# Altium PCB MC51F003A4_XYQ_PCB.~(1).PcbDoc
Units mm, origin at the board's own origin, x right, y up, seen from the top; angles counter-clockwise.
Board outline 55.25 x 35.69 mm, 2 copper layers (Top Layer, Bottom Layer); 32 components, 23 nets, 110 pads, 48 vias.
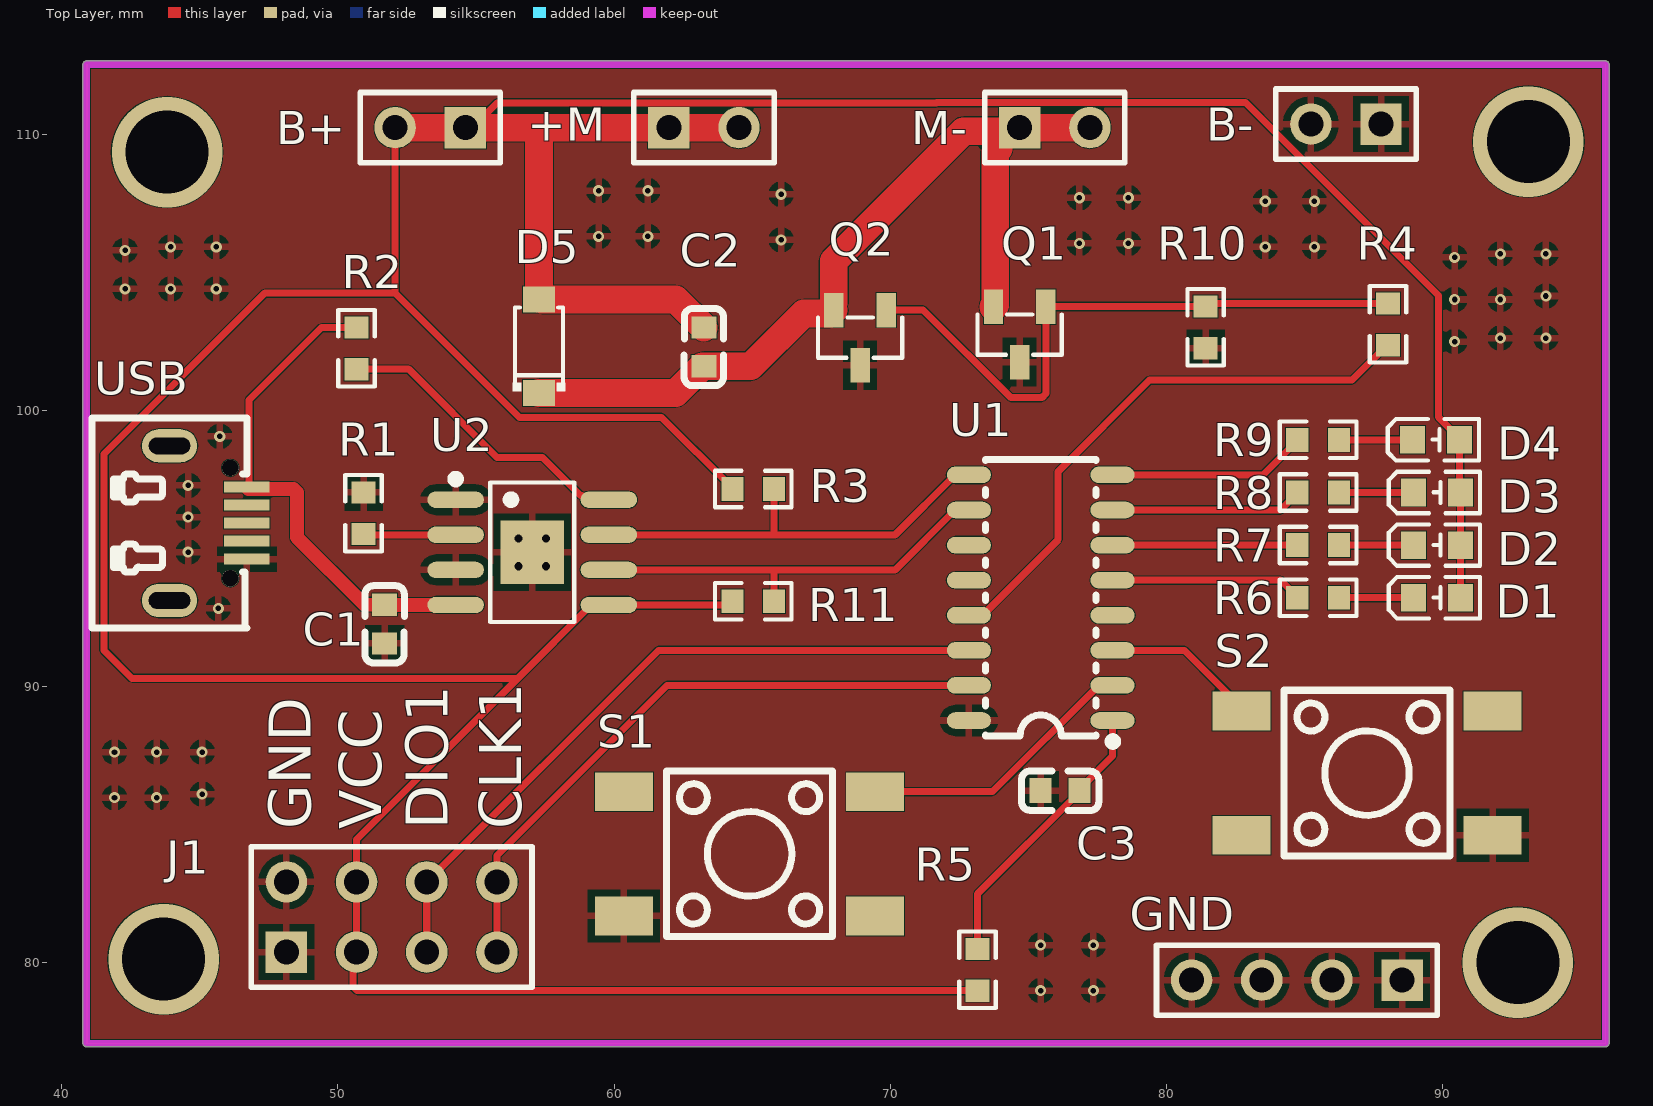
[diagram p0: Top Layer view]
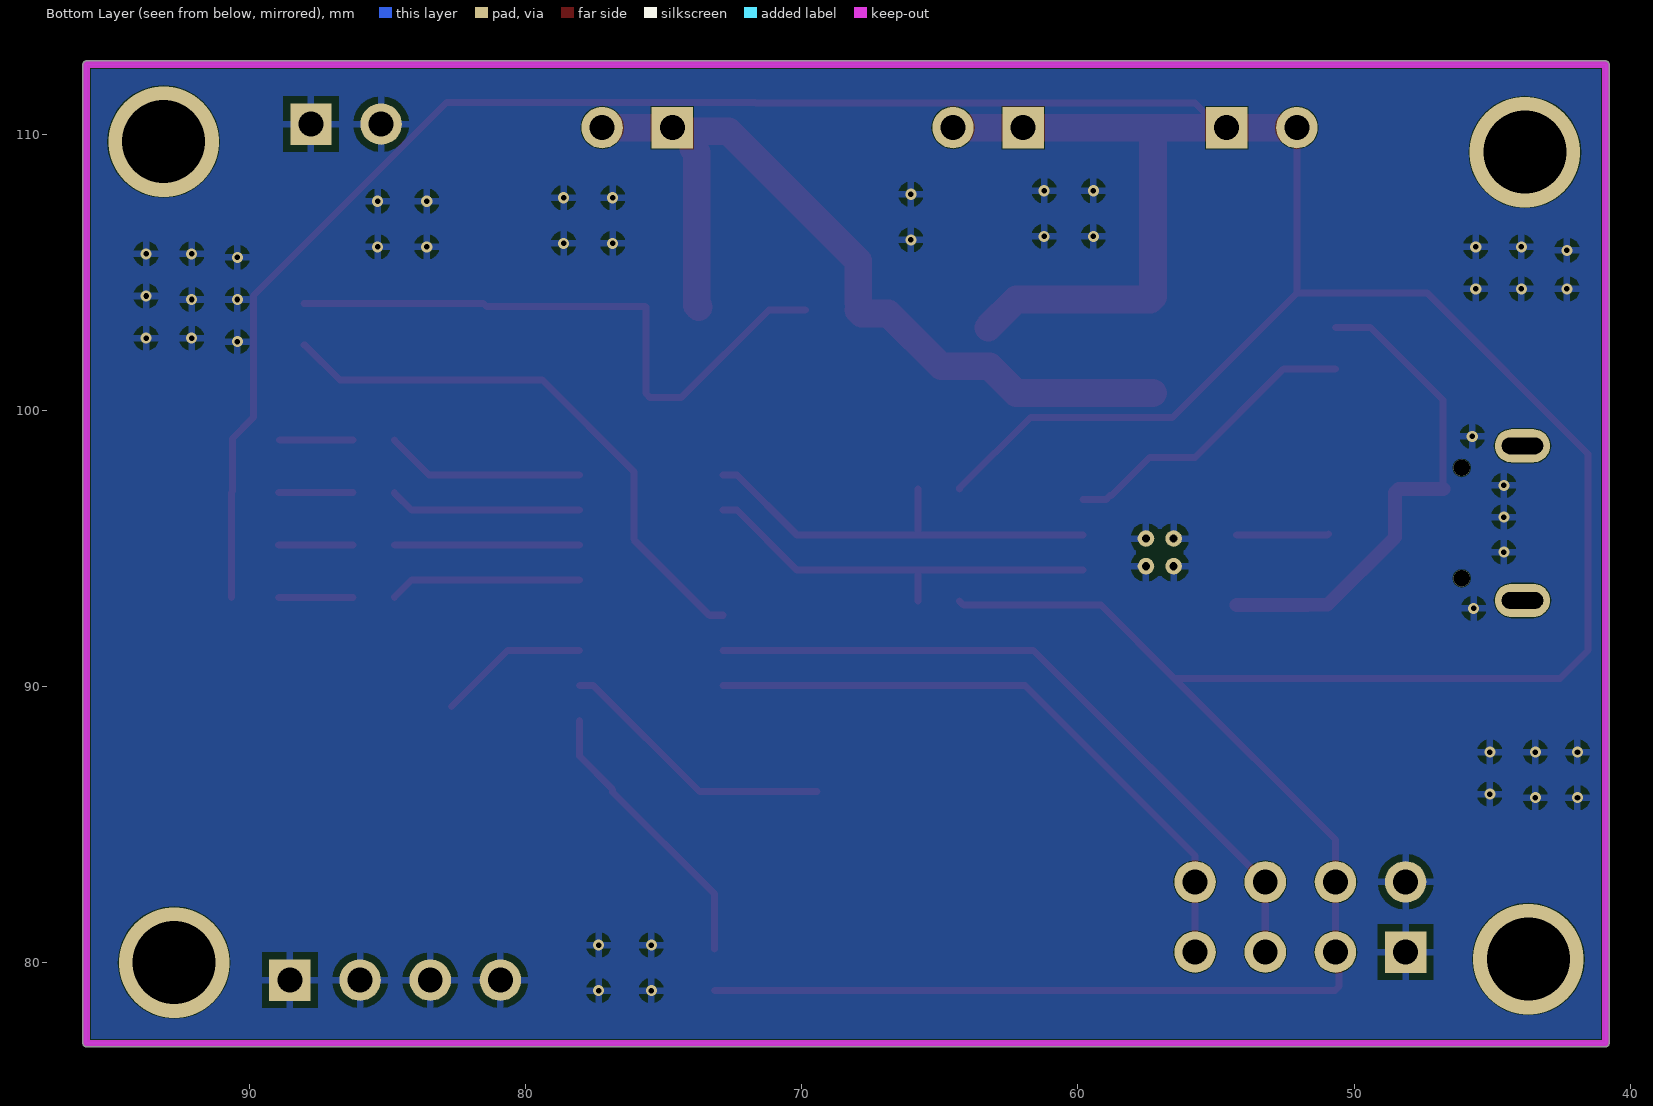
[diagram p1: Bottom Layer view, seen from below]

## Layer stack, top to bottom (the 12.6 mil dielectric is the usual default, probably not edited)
Top Solder: solder mask 0.0102, Solder Resist, Dk 3.5
Top Layer: signal copper 0.0356
Dielectric 1: dielectric 0.32, FR-4, Dk 4.8
Bottom Layer: signal copper 0.0356
Bottom Solder: solder mask 0.0102, Solder Resist, Dk 3.5

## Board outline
40.894,76.962 cw(c40.894,77.089) 40.767,77.089 40.767,112.522 cw(c40.894,112.522) 40.894,112.649 95.885,112.649 cw(c95.885,112.522) 96.012,112.522 96.012,77.089 cw(c95.885,77.089) 95.885,76.962

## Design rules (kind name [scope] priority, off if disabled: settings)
Clearance [All] p1: gap=0.025 ignorepadtopadclearanceinfootprint=FALSE
PolygonConnect [All] p1: connectstyle=Relief reliefconductorwidth=0.254 reliefentries=4 polygonreliefangle="90 Angle" airgapwidth=0.254
RoutingVias [All] p1: holewidth=0.711 width=1.27 viastyle="Through Hole" minholewidth=0.711 minwidth=1.27 maxholewidth=0.711 maxwidth=1.27
SilkToSolderMaskClearance [IsPad] p1: minsilkscreentomaskgap=0 clearancetoexposedcopper=TRUE
SolderMaskExpansion [All] p1: expansion=0.102 istentingtop=FALSE
Width [All] p1: maxlimit=4 minlimit=0.254 preferedwidth=0.254
29 further rules are at their usual default settings.

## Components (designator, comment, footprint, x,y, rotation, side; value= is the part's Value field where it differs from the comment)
B+ "MHDR1X2" HDR1X2 54.61,110.236 r180 top
B- "MHDR1X2" HDR1X2 87.757,110.363 r180 top
C1 "Cap" C0603 51.689,92.264 r90 top value=10uF
C2 "Cap" C0603 63.246,102.297 r90 top value=100pF
C3 "Cap" C0603 76.135,86.233 r180 top value=0.1uF
D1 "LED0" LED0603-FD 89.789,93.218 r180 top
D2 "LED0" LED0603-FD 89.789,95.123 r180 top
D3 "LED0" LED0603-FD 89.789,97.028 r180 top
D4 "LED0" LED0603-FD 89.75,98.933 r180 top
D5 "Diode" SOD-123_L2.8-W1.8-LS3.7-RD 57.277,102.32 r90 top
GND "MHDR1X4" HDR1X4 88.519,79.375 r180 top
J1 "Header 4X2" HDR2X4 48.133,80.391 r0 top
M+ "Header 2" HDR1X2 61.976,110.236 r0 top
M- "Header 2" HDR1X2 74.676,110.236 r0 top
Q1 "NMOS-2" SOT-23-3_L2.9-W1.3-P1.90-LS2.4-BR 74.676,102.743 r90 top
Q2 "NMOS-2" SOT-23-3_L2.9-W1.3-P1.90-LS2.4-BR 68.9,102.632 r90 top
R1 "Res2" R0603 50.927,96.275 r270 top value=5.1K
R2 "Res2" R0603 50.673,102.244 r90 top value=1K
R3 "Res2" R0603 65.033,97.155 r180 top value=1K
R4 "Res2" R0603 88.011,103.115 r90 top value=1K
R5 "Res2" R0603 73.152,79.747 r90 top value=5R
R6 "Res2" R0603 85.48,93.218 r180 top value=510
R7 "Res2" R0603 85.48,95.123 r180 top value=510
R8 "Res2" R0603 85.48,97.028 r180 top value=510
R9 "Res2" R0603 85.48,98.933 r0 top value=510
R10 "Res2" R0603 81.407,103.006 r90 top value=100K
R11 "Res2" R0603 65.033,93.091 r0 top value=1K
S1 "SW-PB" SW-SMD_4P-L6.0-W6.0-P4.50-LS10.0_UK-B0228XXX 64.897,83.947 r180 top
S2 "SW-PB" SW-SMD_4P-L6.0-W6.0-P4.50-LS10.0_UK-B0228XXX 87.249,86.868 r0 top
U1 "MC51F003A4_SOP16" SOP-16_L9.9-W3.9-P1.27-LS6.1-BL 75.438,93.218 r90 top
U2 "TC4056" SOP-8_L4.9-W3.9-P1.27-LS6.0-BL-EP 57.031,94.861 r270 top
USB "MHDR1X5" MICRO-USB-SMD_MICRO-USB-A12 45.301,95.918 r270 top

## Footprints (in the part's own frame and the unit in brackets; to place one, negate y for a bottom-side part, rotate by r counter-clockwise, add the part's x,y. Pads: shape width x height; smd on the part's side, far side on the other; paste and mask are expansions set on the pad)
C0603 [mm]
  rect 0.8x0.9 smd: 1(-0.7,0) 2(0.7,0)
  silkscreen extent -1.41,-0.71 1.39,0.72
HDR1X2 [mm] "Connector; Header; 2 Position"
  rect 1.5x1.5 hole 0.9: 1(0,0)
  round 1.5 hole 0.9: 2(2.54,0)
  silkscreen extent -1.27,-1.27 3.81,1.27
HDR1X4 [mm] "Connector; Header; 4 Position"
  rect 1.5x1.5 hole 0.9: 1(0,0)
  round 1.5 hole 0.9: 2(2.54,0) 3(5.08,0) 4(7.62,0)
  silkscreen extent -1.27,-1.27 8.89,1.27
HDR2X4 [mm] "Connector; Header; 4x2 Position"
  rect 1.5x1.5 hole 0.9: 1(0,0)
  round 1.5 hole 0.9: 2(0,2.54) 3(2.54,0) 4(2.54,2.54) 5(5.08,0) 6(5.08,2.54) 7(7.62,0) 8(7.62,2.54)
  silkscreen extent -1.27,-1.27 8.89,3.81
LED0603-FD [mm]
  rect 0.9x1 smd: 1(-0.85,0) 2(0.85,0)
  silkscreen extent -1.55,-0.75 1.75,0.75
MICRO-USB-SMD_MICRO-USB-A12 [mm]
  rect 0.4x1.65 smd: 1(-1.3,1.4) 2(-0.65,1.4) 3(0,1.4) 4(0.65,1.4) 5(1.3,1.4)
  oval 1.2x2 hole 0.6 slot 1.5 at 90 deg: 6(2.799,-1.4) 7(-2.799,-1.4)
  round 0.6 hole 0.6 unplated: ""(-1.999,0.8) ""(1.999,0.8)
  silkscreen extent -3.8,-4.2 3.8,1.4
R0603 [mm]
  rect 0.806x0.864 smd: 1(-0.753,0) 2(0.753,0)
  silkscreen extent -1.39,-0.66 1.39,0.66
SOD-123_L2.8-W1.8-LS3.7-RD [mm]
  rect 0.95x1.15 smd: 1(-1.693,0) 2(1.693,0)
  silkscreen extent -1.63,-0.94 1.41,0.94
SOP-8_L4.9-W3.9-P1.27-LS6.0-BL-EP [mm]
  oval 0.588x2.045 smd: 1(-1.905,-2.773) 2(-0.635,-2.773) 3(0.635,-2.773) 4(1.905,-2.773) 5(1.905,2.773) 6(0.635,2.773) 7(-0.635,2.773) 8(-1.905,2.773)
  round 0.6 hole 0.3: 9(-0.5,0.5) 9(-0.5,-0.5) 9(0.5,0.5) 9(0.5,-0.5)
  rect 2.29x2.29 smd: 9(0,0)
  silkscreen extent -2.8,-2.92 2.53,1.52
SOP-16_L9.9-W3.9-P1.27-LS6.1-BL [mm]
  oval 0.6x1.6 smd: 1(-4.445,-2.6) 2(-3.175,-2.6) 3(-1.905,-2.6) 4(-0.635,-2.6) 5(0.635,-2.6) 6(1.905,-2.6) 7(3.175,-2.6) 8(4.445,-2.6) 9(4.445,2.6) 10(3.175,2.6) 11(1.905,2.6) 12(0.635,2.6) 13(-0.635,2.6) 14(-1.905,2.6) 15(-3.175,2.6) 16(-4.445,2.6)
  silkscreen extent -5.36,-2.76 5,2
SOT-23-3_L2.9-W1.3-P1.90-LS2.4-BR [mm]
  rect 1.25x0.7 smd: 1(1,-0.95) 2(1,0.95) 3(-1,0)
  silkscreen extent -0.73,-1.53 0.73,1.53
SW-SMD_4P-L6.0-W6.0-P4.50-LS10.0_UK-B0228XXX [mm]
  rect 2.1x1.4 smd: 1(-4.55,2.25) 2(4.55,2.25) 3(-4.55,-2.25) 4(4.55,-2.25)
  silkscreen extent -3,-3 3,3

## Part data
B+ B- M+ M-: "Header, 2-Pin"
C1 C2 C3: "Capacitor"
D1 D2 D3 D4: "Typical INFRARED GaAs LED"
D5: "Default Diode"
GND: "Header, 4-Pin"
J1: "Header, 4-Pin, Dual row"
Q1 Q2: "N-Channel Power MOSFET"
R1 R2 R3 R4 R5 R6 R7 R8 R9 R10 R11: "Resistor"
S1 S2: "Switch"
USB: "Header, 5-Pin"

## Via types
v1: diameter 0.4, hole 0.2, Top Layer to Bottom Layer, 44 vias
v2: diameter 4, hole 3, Top Layer to Bottom Layer, 4 vias

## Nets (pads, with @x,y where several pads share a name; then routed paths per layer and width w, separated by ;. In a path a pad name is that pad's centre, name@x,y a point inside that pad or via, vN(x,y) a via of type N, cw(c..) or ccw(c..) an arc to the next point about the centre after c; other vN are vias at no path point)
B+: B+.1 B+.2 C2.2 D1.1 D2.1 D3.1 D4.1 D5.2 J1.3 J1.4 M+.1 M+.2 R3.2 R5.1 R11.1 U2.5 | length 176.3
  Top Layer w0.254: B+.2 52.07,104.246 ; B+.1@54.864,110.236 55.753,111.125 71.659,111.125 71.673,111.138 82.85,111.138 89.832,104.156 89.832,99.751 90.6,98.983 D4.1 90.6,97.067 D3.1 D2.1 D1.1 ; D5.2@57.277,104.113 D5.2@57.377,104.013 ; R11.1 64.145,92.956 U2.5 59.166,92.956 56.506,90.297 ; R3.2 64.28,97.184 61.716,99.747 56.569,99.747 52.07,104.246 ; R5.1 50.695,78.994 50.546,79.143 50.546,80.264 J1.3 J1.4 50.673,84.464 56.506,90.297 ; 52.07,104.246 47.35,104.246 41.529,98.425 41.529,91.313 42.545,90.297 56.506,90.297
  Top Layer w1: B+.2 B+.1 54.864,110.236 57.277,110.236 ; D5.2@57.277,104.113 57.277,110.236 ; D5.2@57.377,104.013 62.23,104.013 C2.2 ; M+.2 M+.1 57.277,110.236
BAT_F_IN: R3.1 U1.9 U2.7 | length 15.6
  Top Layer w0.254: U2.7 65.786,95.496 ; R3.1 65.786,95.496 ; U1.9 72.338,97.663 70.171,95.496 65.786,95.496
BAT_FINISH_IN: R11.2 U1.10 U2.6 | length 15.1
  Top Layer w0.254: U2.6 65.786,94.226 ; R11.2 65.786,94.226 ; U1.10 72.338,96.393 70.171,94.226 65.786,94.226
CLK1: J1.7 J1.8 U1.15 | length 23.1
  Top Layer w0.254: J1.7 55.753,83.892 61.904,90.043 U1.15
DIO1: J1.5 J1.6 U1.14 | length 25.6
  Top Layer w0.254: J1.5 J1.6 61.595,91.313 U1.14
GND: B-.1 B-.2 C1.1 C3.2 GND.1 GND.2 GND.3 GND.4 J1.1 J1.2 Q1.3 Q2.3 R1.1 R10.1 S1.2 S2.4 U1.16 U2.1 U2.3 U2.9 USB.5
  other v1: 75.438,78.994 77.343,78.994 75.438,80.645 77.343,80.645 41.91,85.979 43.434,85.979 45.085,86.106 41.91,87.63 43.434,87.63 45.085,87.63 45.667,92.83 44.577,94.869 44.577,96.139 44.577,97.282 45.72,99.06 90.424,102.489 92.075,102.616 93.726,102.616 90.424,104.013 92.075,104.013 93.726,104.14 42.291,104.394 43.942,104.394 45.593,104.394 90.424,105.537 92.075,105.664 93.726,105.664 42.291,105.791 43.942,105.918 45.593,105.918 83.566,105.918 85.344,105.918 76.835,106.045 78.613,106.045 66.04,106.172 59.436,106.299 61.214,106.299 83.566,107.569 85.344,107.569 76.835,107.696 78.613,107.696 66.04,107.823 59.436,107.95 61.214,107.95
LED1: R6.2 U1.5 | length 7
  Top Layer w0.254: U1.5 84.12,93.853 84.727,93.247 R6.2
LED2: R7.2 U1.6 | length 6.7
  Top Layer w0.254: U1.6 R7.2
LED3: R8.2 U1.7 | length 7
  Top Layer w0.254: U1.7 84.12,96.393 84.727,96.999 R8.2
LED4: R9.1 U1.8 | length 7.2
  Top Layer w0.254: U1.8 83.485,97.663 84.727,98.904 R9.1
M_IN: R4.1 U1.13 | length 20.7
  Top Layer w0.254: U1.13 73.338,92.583 76.072,95.317 76.072,97.789 79.375,101.092 86.712,101.092 87.982,102.362 R4.1
NetC2_1: C2.1 D5.1 M-.1 M-.2 Q1.2 Q2.2 | length 31.4
  Top Layer w0.254: 73.914,109.474 74.549,110.109 M-.1
  Top Layer w1: D5.1 62.227,100.628 C2.1@63.196,101.597 ; C2.1 64.946,101.597 66.856,103.507 67.825,103.507 Q2.2 ; Q2.2@67.945,103.886 67.945,105.41 72.644,110.109 M-.1@74.549,110.109 ; Q1.2 73.787,103.804 73.787,109.347 73.914,109.474 ; M-.1 M-.2
NetC3_1: C3.1 R5.2 U1.1 | length 10.3
  Top Layer w0.254: R5.2 73.152,82.5 76.835,86.183 C3.1 76.835,86.283 78.038,87.486 U1.1
NetD1_2: D1.2 R6.1 | length 2.7
  Top Layer w0.254: R6.1 D1.2
NetD2_2: D2.2 R7.1 | length 2.7
  Top Layer w0.254: R7.1 D2.2
NetD3_2: D3.2 R8.1 | length 2.7
  Top Layer w0.254: R8.1 D3.2
NetD4_2: D4.2 R9.2 | length 2.7
  Top Layer w0.254: R9.2 D4.2
NetQ1_1: Q1.1 Q2.1 R4.2 R10.2 | length 22.7
  Top Layer w0.254: Q2.1 71.181,103.632 74.356,100.457 75.477,100.457 75.626,100.606 Q1.1 75.642,103.759 R10.2 81.516,103.868 R4.2
NetR1_2: R1.2 U2.2 | length 3.3
  Top Layer w0.254: R1.2 50.952,95.496 U2.2
NetR2_1: R2.1 U2.8 | length 11.1
  Top Layer w0.254: R2.1 52.56,101.491 55.753,98.298 57.404,98.298 58.782,96.92 58.831,96.92 58.985,96.766 U2.8
NetS1_1: S1.3 U1.2 | length 10.2
  Top Layer w0.254: S1.3 73.692,86.197 77.538,90.043 U1.2
NetS2_1: S2.1 U1.3 | length 5.5
  Top Layer w0.254: U1.3 80.645,91.313 S2.1@82.677,89.281
P+: C1.2 R2.2 U2.4 USB.1 | length 18.4
  Top Layer w0.254: USB.1 USB.1@46.764,97.155 ; USB.1@46.709,97.218 46.782,97.291 46.782,100.376 49.403,102.997 R2.2 ; C1.2 C1.2@51.697,92.956
  Top Layer w0.5: USB.1@46.764,97.155 48.387,97.155 48.514,97.028 48.514,95.405 50.955,92.964 C1.2 ; C1.2@51.697,92.956 U2.4
pads on no net: S1.1 S1.4 S2.2 S2.3 U1.4 U1.11 U1.12 USB. USB.2 USB.3 USB.4 USB.6 USB.7
copper on no net:
  other v2: 92.71,80.01 43.688,80.137 43.815,109.347 93.091,109.728

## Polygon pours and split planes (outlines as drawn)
GND on Top Layer "GND_L01_P021" (solid, pour order 21): 40.894,112.522 95.885,112.522 95.885,77.089 40.894,77.089
GND on Top Layer "NONET_L01_P018" (solid, shelved, pour order 18): 40.915,112.508 40.915,77.11 40.894,77.089 95.885,77.089 95.885,112.522
GND on Top Layer "NONET_L01_P016" (solid, shelved, pour order 16): 40.894,112.522 40.894,77.089 95.885,77.089 95.885,112.522
GND on Top Layer "NONET_L01_P001" (solid, shelved, pour order 1): 74.549,92.837
GND on Bottom Layer "GND_L02_P020" (solid, pour order 20): 40.894,112.522 95.885,112.522 95.885,77.089 40.894,77.089
GND on Bottom Layer "NONET_L02_P019" (solid, shelved, pour order 19): 40.894,112.522 40.894,77.089 95.885,77.089 95.885,112.522
GND on Bottom Layer "NONET_L02_P015" (solid, shelved, pour order 15): 40.894,112.522 40.894,77.089 95.885,77.089 95.885,112.522

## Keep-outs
Keep-Out Layer:
  lines w0.254: 40.894,77.089 40.894,112.522 95.885,112.522 95.885,77.089 40.894,77.089

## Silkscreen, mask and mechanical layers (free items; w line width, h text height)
Top Overlay:
  text "GND" at 49.022,84.836 h1.52 r90
  text "VCC" at 51.562,84.836 h1.52 r90
  text "DIO1" at 53.975,84.836 h1.52 r90
  text "CLK1" at 56.642,84.836 h1.52 r90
